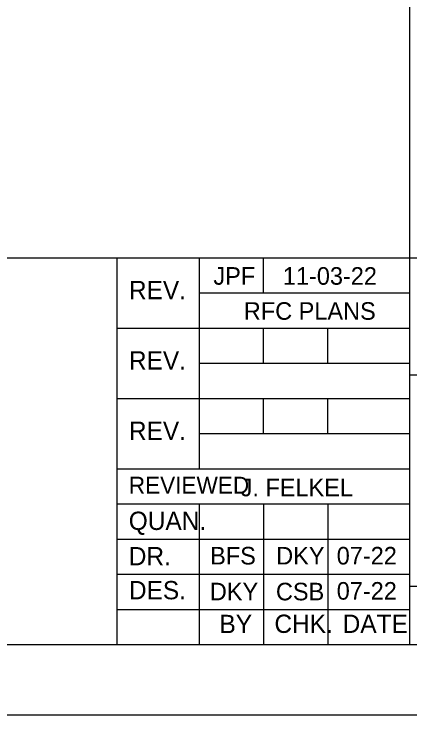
# Model space of a CAD drawing. Extents: x 1970675.2 to 1970711.3, y 796145.2 to 796167.2.
# Drawn here: x 1970702.503 to 1970705.319, y 796145.246 to 796150.229 of the extents above; entities that cross this region are included whole.
import ezdxf

# ---------------------------------------------------------------- set-up
doc = ezdxf.new("R2010")
doc.units = 0
for name, color, linetype in [('BR_BORDER LINES', 7, 'Continuous'), ('BR_TEXT', 7, 'Continuous'), ('Level 31', 7, 'Continuous')]:
    doc.layers.add(name, color=color, linetype=linetype)

msp = doc.modelspace()

# ---------------------------------------------------------------- linework, layer by layer
at = {"layer": 'BR_BORDER LINES'}
for p, q in [((1970705.3189, 796145.7463), (1970705.3189, 796151.0229)), ((1970697.8703, 796148.4964), (1970703.2355, 796148.4964)), ((1970703.2355, 796145.7463), (1970703.2355, 796148.4964)), ((1970703.2355, 796148.4964), (1970710.7358, 796148.4964)), ((1970703.8189, 796148.4964), (1970703.8189, 796146.9963)), ((1970704.2772, 796148.2464), (1970704.2772, 796148.4964)), ((1970703.8189, 796148.2464), (1970705.3189, 796148.2464)), ((1970703.2355, 796147.9964), (1970705.3189, 796147.9964)), ((1970704.2772, 796147.7464), (1970704.2772, 796147.9964)), ((1970704.7356, 796147.7464), (1970704.7356, 796147.9964)), ((1970703.8189, 796147.7464), (1970705.3189, 796147.7464)), ((1970705.3189, 796147.663), (1970705.3189, 796147.663)), ((1970705.3189, 796147.663), (1970710.736, 796147.663)), ((1970703.2355, 796147.4964), (1970705.3189, 796147.4964)), ((1970704.2772, 796147.2463), (1970704.2772, 796147.4964)), ((1970704.7356, 796147.2463), (1970704.7356, 796147.4964)), ((1970703.8189, 796147.2463), (1970705.3189, 796147.2463)), ((1970703.2355, 796146.9963), (1970705.3189, 796146.9963)), ((1970703.2355, 796146.7463), (1970705.3189, 796146.7463)), ((1970703.8189, 796146.7463), (1970703.8189, 796145.7463)), ((1970704.2772, 796146.7463), (1970704.2772, 796145.7463)), ((1970704.7356, 796146.7463), (1970704.7356, 796145.7463)), ((1970703.2355, 796146.4963), (1970705.3189, 796146.4963)), ((1970703.2355, 796146.2463), (1970705.3189, 796146.2463)), ((1970705.3189, 796146.163), (1970710.7358, 796146.163)), ((1970703.2355, 796145.9963), (1970705.3189, 796145.9963)), ((1970677.0698, 796145.7463), (1970710.7358, 796145.7463))]:
    msp.add_line(p, q, dxfattribs=at)
at = {"layer": 'Level 31'}
msp.add_lwpolyline([(1970675.2365, 796167.2463), (1970675.2365, 796145.2464), (1970711.2364, 796145.2464), (1970711.2364, 796167.2463)], dxfattribs=at)

# ---------------------------------------------------------------- texts
at = {"layer": 'BR_TEXT'}
for s, height, p in [('JPF', 0.12499, (1970703.9209, 796148.3043)), ('11-03-22', 0.12499, (1970704.415, 796148.3043)), ('REV.', 0.13001, (1970703.3202, 796148.2018)), ('RFC PLANS', 0.12499, (1970704.1374, 796148.0553)), ('REV.', 0.13001, (1970703.3202, 796147.7018)), ('REV.', 0.13001, (1970703.3202, 796147.2018)), ('REVIEWED', 0.12, (1970703.3195, 796146.8198)), ('J. FELKEL', 0.12499, (1970704.1145, 796146.8007)), ('QUAN.', 0.13001, (1970703.3189, 796146.5615)), ('DR.', 0.13001, (1970703.3191, 796146.31)), ('BFS', 0.12499, (1970703.8978, 796146.316)), ('DKY', 0.12499, (1970704.3677, 796146.316)), ('07-22', 0.12499, (1970704.798, 796146.316)), ('DES.', 0.13001, (1970703.3202, 796146.0686)), ('DKY', 0.12499, (1970703.8957, 796146.0612)), ('CSB', 0.12499, (1970704.3656, 796146.0612)), ('07-22', 0.12499, (1970704.798, 796146.066)), ('BY', 0.13001, (1970703.9642, 796145.8283)), ('CHK.', 0.13001, (1970704.355, 796145.8296)), ('DATE', 0.13001, (1970704.8402, 796145.8297))]:
    msp.add_text(s, height=height, dxfattribs=at).set_placement(p)

doc.saveas('drawing.dxf')
